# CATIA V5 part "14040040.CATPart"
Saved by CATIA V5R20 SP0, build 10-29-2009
Part number: 14040040
Definition: NONE
Nomenclature: 14040040
Source: Unknown
Description: 14040040
Bounding box of the stored display mesh (mm): x -20 to 80, y -34 to 23.924, z -24.1 to 24.1
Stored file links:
  C:\Users\Utente\Desktop\IO LAVORO\3D X SITO CF\X SITO\PLASTICA\RF2\14040040.CATPart
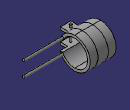
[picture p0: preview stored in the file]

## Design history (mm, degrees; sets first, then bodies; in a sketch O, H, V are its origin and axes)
Body1 "14040040" (main body)
  Solid1: solid without history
